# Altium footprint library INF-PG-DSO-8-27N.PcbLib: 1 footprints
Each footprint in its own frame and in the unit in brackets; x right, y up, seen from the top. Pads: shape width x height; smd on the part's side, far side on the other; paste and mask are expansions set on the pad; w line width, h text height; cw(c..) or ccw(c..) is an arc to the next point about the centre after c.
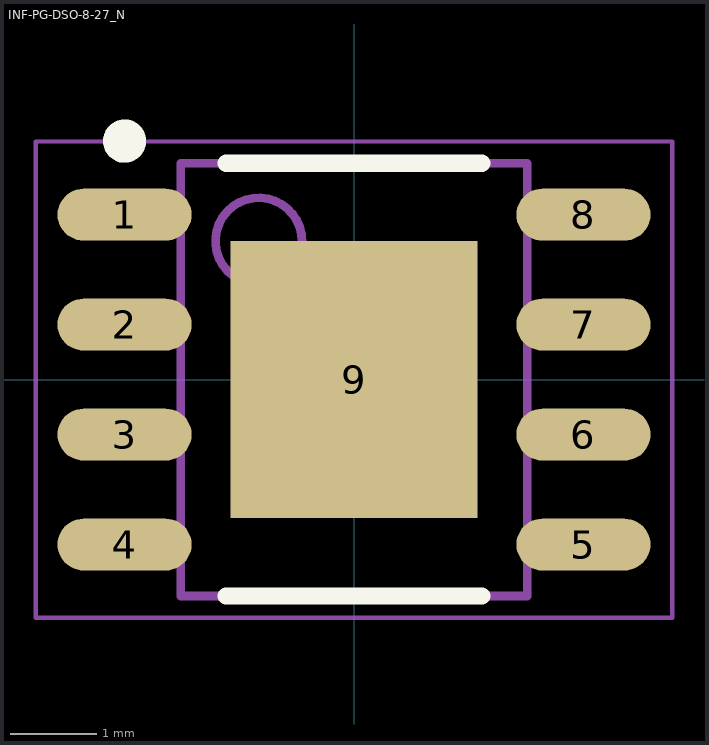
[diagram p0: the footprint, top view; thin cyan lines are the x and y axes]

## INF-PG-DSO-8-27_N [mm] "SOP, 8-Leads, Body 4.9x3.9mm, Pitch 1.27mm, Thermal Pad 3.2x2.85mm, IPC Medium Density"
height 1.7
pads (9):
  oval 1.55x0.6 smd: 1(-2.65,1.905) 2(-2.65,0.635) 3(-2.65,-0.635) 4(-2.65,-1.905) 5(2.65,-1.905) 6(2.65,-0.635) 7(2.65,0.635) 8(2.65,1.905)
  rect 2.85x3.2 smd: 9(0,0)
Top Overlay:
  circle w0.25: c-2.65,2.755 r0.125
  lines w0.2: -1.475,-2.5 1.475,-2.5 ; -1.475,2.5 1.475,2.5
Mechanical 13:
  circle w0.1: c-1.1,1.6 r0.5
  lines w0.1: -2,-2.5 2,-2.5 2,2.5 -2,2.5 -2,-2.5
Mechanical 15:
  lines w0.05: -3.675,-2.75 3.675,-2.75 3.675,2.75 -3.675,2.75 -3.675,-2.75
  lines w0.1: -0.5,0 0.5,0 ; 0,-0.5 0,0.5
3D body: height 1.7, standoff 0, extent -2,-2.5 2,2.5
